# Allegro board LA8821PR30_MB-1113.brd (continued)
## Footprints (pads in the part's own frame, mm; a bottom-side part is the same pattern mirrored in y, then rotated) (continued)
BELLW_80019-1021_52P
  round 1.6 hole 1.6 unplated: (-25.55,-1.8) (1.95,-1.8)
  oval 0.61x2.007 smd: 1(0,0) 3(-0.8,0) 5(-1.6,0) 7(-2.4,0) 9(-3.2,0) 11(-4,0) 13(-4.8,0) 15(-5.6,0) 17(-9.6,0) 19(-10.4,0) 21(-11.2,0) 23(-12,0) 25(-12.8,0) 27(-13.6,0) 29(-14.4,0) 31(-15.2,0) 33(-16,0) 35(-16.8,0) 37(-17.6,0) 39(-18.4,0) 41(-19.2,0) 43(-20,0) 45(-20.8,0) 47(-21.6,0) 49(-22.4,0) 51(-23.2,0)
  oval 0.61x1.524 hole 0.457x0.914: 2(-0.4,-2.4) 4(-1.2,-2.4) 6(-2,-2.4) 8(-2.8,-2.4) 10(-3.6,-2.4) 12(-4.4,-2.4) 14(-5.2,-2.4) 16(-6,-2.4) 18(-10,-2.4) 20(-10.8,-2.4) 22(-11.6,-2.4) 24(-12.4,-2.4) 26(-13.2,-2.4) 28(-14,-2.4) 30(-14.8,-2.4) 32(-15.6,-2.4) 34(-16.4,-2.4) 36(-17.2,-2.4) 38(-18,-2.4) 40(-18.8,-2.4) 42(-19.6,-2.4) 44(-20.4,-2.4) 46(-21.2,-2.4) 48(-22,-2.4) 50(-22.8,-2.4) 52(-23.6,-2.4)
  oval 1.549x2.769 hole 0.787x2.007: 53(5.075,-8.4) 54(-28.675,-8.4)
BSS138-G_SOT23-3
  oval 1.016x1.524 smd: 1(0,0) 2(0.965,2.083) 3(-0.965,2.083)
BSS138_NL_SOT23-3
  oval 1.016x1.524 smd: 1(0,0) 2(0.965,2.083) 3(-0.965,2.083)
BZT52-B5V6S_SOD323-2
  rect 0.559x0.813 smd: 1(0,0) 2(2.305,0)
C_0402NEW
  rect 0.508x0.559 smd: 1(0,0) 2(0.914,0)
C_0603NEW
  rect 0.635x0.889 smd: 1(0,0) 2(1.397,0)
C_0805NEW
  rect 0.813x1.397 smd: 1(0,0) 2(1.702,0)
C_B
  rect 1.549x2.464 smd: 1(0,0) 2(3.378,0)
C_B2
  rect 1.346x2.692 smd: 1(0,0) 2(-2.75,0)
C_D2
  rect 2.388x2.794 smd: 1(0,0) 2(6.4,0)
C_D2E
  rect 2.388x2.896 smd: 1(0,0) 2(6.1,0)
D_EC31QS04
  rect 2.235x2.032 smd: 1(1.9,0) 2(-1.9,0)
D_RCLAMP0524PPTCT
  oval 0.203x0.686 smd: 1(0,0) 2(0.5,0) 4(1.5,0) 5(2,0) 6(2,0.875) 7(1.5,0.875) 9(0.5,0.875) 10(0,0.875)
  oval 0.406x1.549 smd: 3(1,0.437)
DE303DLHCTR_LGA14_3X5
  oval 0.61x1.092 smd: 1(0,0) 2(0.8,0) 3(1.6,0) 4(2.4,0) 5(3.2,0) 6(4,0) 8(4,2.2) 9(3.2,2.2) 10(2.4,2.2) 11(1.6,2.2) 12(0.8,2.2) 13(0,2.2)
  oval 1.092x0.61 smd: 7(4.1,1.1) 14(-0.1,1.1)
DMN66D0LDW-7_SOT363-6
  oval 0.432x0.61 smd: 1(0,0) 2(0.65,0) 3(1.3,0) 4(1.3,1.9) 5(0.65,1.9) 6(0,1.9)
E-T_1001-F36E-03R_36P
  round 0.711 hole 0.711 unplated: (-1.25,-2.425) (9.75,-2.425)
  oval 0.381x1.143 smd: 1(0,0) 2(0,-4.85) 35(8.5,0) 36(8.5,-4.85)
  oval 0.254x1.143 smd: 3(0.5,0) 4(0.5,-4.85) 5(1,0) 6(1,-4.85) 7(1.5,0) 8(1.5,-4.85) 9(2,0) 10(2,-4.85) 11(2.5,0) 12(2.5,-4.85) 13(3,0) 14(3,-4.85) 15(3.5,0) 16(3.5,-4.85) 17(4,0) 18(4,-4.85) 19(4.5,0) 20(4.5,-4.85) 21(5,0) 22(5,-4.85) 23(5.5,0) 24(5.5,-4.85) 25(6,0) 26(6,-4.85) 27(6.5,0) 28(6.5,-4.85) 29(7,0) 30(7,-4.85) 31(7.5,0) 32(7.5,-4.85) 33(8,0) 34(8,-4.85)
  custom 0.4x0.4 smd: 37(10.7,-2.425) 38(-2.2,-2.425)
EMI-79X138
  rect 2.007x3.505 smd: 1(0,0)
F_1206L150PR
  rect 0.991x1.803 smd: 1(0,0) 2(2.8,0)
F_1812L075-24DR
  rect 1.778x3.15 smd: 1(0,0) 2(5.23,0)
FDMC7672S_MLP8-5
  oval 0.432x0.711 smd: 1(0,0) 2(0.65,0) 3(1.3,0) 4(1.95,0)
  custom 0.537x0.537 smd: 5(0.975,2.075)
FDMS6673BZ_POWER56-8-5
  oval 0.61x1.27 smd: 1(0,0) 2(1.27,0) 3(2.54,0) 4(3.81,0)
  custom 1.105x1.105 smd: 5(1.905,3.715)
FDV301N_NL_SOT23-3
  oval 1.016x1.524 smd: 1(0,0) 2(0.965,2.083) 3(-0.965,2.083)
FIDUCIAL_C40M80
  round 1.016 smd: 1(0,0)
FOX_GS73091-10272-7H_9P-T
  rect 0.66x5.004 smd: 1(0,0) 2(-1.5,0) 3(-3,0) 4(-4.5,0) 5(-6,0) 6(-7.5,0) 7(-9,0) 8(-10.5,0) 9(-12,0)
  rect 2.489x2.997 smd: 10(-14.5,4.45) 11(2.5,4.45)
G547I2P81U_MSOP8
  oval 0.381x1.549 smd: 1(0,0) 2(0.65,0) 3(1.3,0) 4(1.95,0) 5(1.95,4.37) 6(1.3,4.37) 7(0.65,4.37) 8(0,4.37)
GLZ5P1B_LL34-2
  oval 0.889x2.007 smd: 1(0,0) 2(3.1,0)
H_2P0N
  round 2.007 hole 2.007 unplated: (0,0)
H_2P0X2P5N
  oval 2.007x2.489 hole 2.007x2.489 unplated: (0,0)
H_2P3
  round 2.819 hole 2.311: 1(0,0)
H_3P2
  round 3.708 hole 3.2: 1(0,0)
H_4P0
  round 4.496 hole 3.988: 1(0,0)
H_4P5N
  round 4.496 hole 4.496 unplated: (0,0)
HRS_UPFL-R-SMT-1-10_3P
  rect 1.041x2.21 smd: 1(0,0) 3(2.95,0)
  rect 0.991x1.041 smd: 2(1.475,1.525)
INA199A2DCKR_SC70-6
  oval 0.406x0.889 smd: 1(0,0) 2(0.65,0) 3(1.3,0) 4(1.3,2.2) 5(0.65,2.2) 6(0,2.2)
IP4223CZ6_SO6
  oval 0.508x1.422 smd: 1(0,0) 2(0.95,0) 3(1.9,0) 4(1.9,2.35) 5(0.95,2.35) 6(0,2.35)
ISL9519HRTZ-T_TQFN28_4X4
  oval 0.203x1.092 smd: 1(0,0) 2(0.4,0) 3(0.8,0) 4(1.2,0) 5(1.6,0) 6(2,0) 7(2.4,0) 15(2.4,3.9) 16(2,3.9) 17(1.6,3.9) 18(1.2,3.9) 19(0.8,3.9) 20(0.4,3.9) 21(0,3.9)
  oval 1.092x0.203 smd: 8(3.15,0.75) 9(3.15,1.15) 10(3.15,1.55) 11(3.15,1.95) 12(3.15,2.35) 13(3.15,2.75) 14(3.15,3.15) 22(-0.75,3.15) 23(-0.75,2.75) 24(-0.75,2.35) 25(-0.75,1.95) 26(-0.75,1.55) 27(-0.75,1.15) 28(-0.75,0.75)
  rect 2.388x2.388 smd: 29(1.2,1.95)
ISL95835HRTZ-T_TQFN40_5X5
  oval 0.203x0.991 smd: 1(0,0) 2(0.4,0) 3(0.8,0) 4(1.2,0) 5(1.6,0) 6(2,0) 7(2.4,0) 8(2.8,0) 9(3.2,0) 10(3.6,0) 21(3.6,5.001) 22(3.2,5.001) 23(2.8,5.001) 24(2.4,5.001) 25(2,5.001) 26(1.6,5.001) 27(1.2,5.001) 28(0.8,5.001) 29(0.4,5.001) 30(0,5.001)
  oval 0.991x0.203 smd: 11(4.3,0.7) 12(4.3,1.1) 13(4.3,1.5) 14(4.3,1.9) 15(4.3,2.3) 16(4.3,2.7) 17(4.3,3.1) 18(4.3,3.5) 19(4.3,3.9) 20(4.3,4.3) 31(-0.7,4.3) 32(-0.7,3.9) 33(-0.7,3.5) 34(-0.7,3.1) 35(-0.7,2.7) 36(-0.7,2.3) 37(-0.7,1.9) 38(-0.7,1.5) 39(-0.7,1.1) 40(-0.7,0.7)
  rect 3.607x3.607 smd: 41(1.8,2.5)
IVY-BRIDGE_BGA_1023P
  round 0.381 smd: A4(1.154,-0.101) A5(1.804,-0.101) A57(27.577,-0.101) A58(28.228,-0.101) A59(28.878,-0.101) A61(29.528,-0.101) BC1(0.177,-20.581) BC61(29.528,-20.577) BD1(0.101,-21.227) BD3(0.751,-21.227) BD59(28.878,-21.227) BD61(29.528,-21.227) BE1(0.101,-21.878) BE3(0.751,-21.878) BE4(1.401,-21.878) BE58(28.228,-21.878) BE59(28.878,-21.878) BE61(29.528,-21.878) BG1(0.101,-22.528) BG3(0.751,-22.528) BG4(1.401,-22.528) BG5(2.051,-22.392) BG57(27.577,-22.528) BG58(28.228,-22.528) BG59(28.878,-22.528) BG61(29.528,-22.528) C3(0.504,-0.504) C4(1.194,-0.751) C58(28.228,-0.751) C59(28.878,-0.751) C61(29.528,-0.751) D1(0.101,-1.144) D3(0.751,-1.227) D59(28.878,-1.401) D61(29.528,-1.401) E1(0.101,-1.794) E61(29.528,-2.051)
  round 0.305 smd: A8(3.181,0) A9(4.045,0) A11(5.157,0) A13(6.021,0) A15(7.133,0) A17(7.997,0) A19(9.109,0) A21(9.973,0) A23(11.086,0) A25(12.041,0) A26(12.691,0) A28(13.341,0) A29(13.991,0) A31(14.642,0) A33(15.292,0) A34(15.942,0) A35(16.592,0) A37(17.243,0) A38(17.893,0) A39(18.543,0) A40(19.193,0) A42(19.854,0) A44(20.966,0) A45(21.83,0) A48(22.942,0) A49(23.806,0) A51(24.918,0) A53(25.782,0) A55(26.895,0) AA1(0,-9.748) AA3(0.729,-9.748) AA4(1.374,-9.85) AA6(2.246,-9.912) AA7(2.897,-9.912) AA8(3.547,-9.912) AA10(4.197,-9.912) AA11(4.847,-9.912) AA13(5.498,-9.912) AA14(6.148,-9.912) AA50(24.08,-9.812) AA51(24.73,-9.812) AA52(25.381,-9.812) AA53(26.031,-9.812) AA55(26.681,-9.812) AA56(27.331,-9.812) AB50(24.08,-10.462) AB51(24.73,-10.462) AB52(25.381,-10.462) AB53(26.031,-10.462) AB55(26.681,-10.462) AB56(27.331,-10.462) AB58(28.204,-10.137) AB59(28.9,-10.239) AB61(29.629,-10.066) AC1(0,-10.612) AC3(0.729,-10.612) AC4(1.374,-10.51) AC6(2.566,-10.902) AC8(3.217,-10.902) AC9(3.867,-10.902) AC10(4.517,-10.902) AC12(5.167,-10.902) AC61(29.629,-10.716) AD2(0.381,-11.168) AD4(1.425,-11.168) AD50(24.08,-11.248) AD51(24.73,-11.248) AD52(25.381,-11.248) AD53(26.031,-11.248) AD55(26.681,-11.248) AD56(27.331,-11.248) AD58(28.204,-11.013) AD59(28.9,-11.115) AD61(29.629,-11.367) AE6(2.241,-11.468) AE7(2.892,-11.468) AE8(3.542,-11.468) AE10(4.192,-11.468) AE11(4.842,-11.468) AF1(0,-11.724) AF3(0.729,-11.724) AF4(1.374,-11.826) AF50(24.08,-12.066) AF51(24.73,-12.066) AF52(25.381,-12.066) AF53(26.031,-12.066) AF55(26.681,-12.066) AF56(27.331,-12.066) AF58(28.204,-11.902) AF59(28.9,-12.004) AF61(29.629,-12.017) AG1(0,-12.588) AG3(0.729,-12.588) AG4(1.374,-12.486) AG6(2.272,-12.459) AG7(2.922,-12.459) AG8(3.572,-12.459) AG10(4.222,-12.459) AG11(4.873,-12.459) AG55(26.681,-12.717) AG56(27.331,-12.717) AG58(28.254,-12.664) AG59(28.9,-12.766) AG61(29.629,-12.766) AH2(0.381,-13.144) AH4(1.425,-13.144) AH58(28.204,-13.322) AH60(29.248,-13.322) AJ6(2.272,-13.449) AJ7(2.922,-13.449) AJ8(3.572,-13.449) AJ10(4.222,-13.449) AJ11(4.873,-13.449) AK1(0,-13.7) AK3(0.729,-13.7) AK4(1.374,-13.802) AK55(26.77,-13.707) AK56(27.42,-13.707) AK58(28.254,-13.98) AK59(28.9,-13.879) AK61(29.629,-13.879) AL1(0,-14.564) AL3(0.729,-14.564) AL4(1.374,-14.462) AL6(2.221,-14.44) AL7(2.871,-14.44) AL8(3.521,-14.44) AL10(4.172,-14.44) AL11(4.822,-14.44) AL13(5.472,-14.44) AL14(6.122,-14.44) AL15(6.773,-14.44) AL58(28.254,-14.641) AL59(28.9,-14.742) AL61(29.629,-14.742) AM2(0.381,-15.12) AM4(1.425,-15.12) AM13(5.472,-15.287) AM14(6.122,-15.287) AM15(6.773,-15.287) AM58(28.204,-15.298) AM60(29.248,-15.298) AN1(0,-15.676) AN3(0.729,-15.676) AN4(1.374,-15.778) AN54(26.3,-15.545) AN55(26.95,-15.545) AN57(27.601,-15.545) AN58(28.254,-15.956) AN59(28.9,-15.855) AN61(29.629,-15.855) AP6(2.302,-15.852) AP7(2.952,-15.852) AP8(3.603,-15.852) AP10(4.253,-15.852) AP11(4.903,-15.852) AP50(24.024,-16.11) AP51(24.675,-16.11) AP52(25.325,-16.11) AP53(25.975,-16.11) AP55(26.625,-16.11) AP56(27.276,-16.11) AR1(0,-16.54) AR3(0.729,-16.54) AR4(1.374,-16.438) AR6(2.292,-16.843) AR7(2.942,-16.843) AR8(3.593,-16.843) AR10(4.243,-16.843) AR11(4.893,-16.741) AR13(5.776,-16.696) AR14(6.342,-16.371) AR17(8.18,-16.447) AR19(9.17,-16.447) AR21(10.161,-16.43) AR22(10.726,-16.755) AR26(12.564,-16.498) AR28(13.554,-16.396) AR30(14.545,-16.704) AR32(15.111,-16.378) AR34(16.101,-16.427) AR36(17.092,-16.427) AR40(18.929,-16.371) AR41(19.495,-16.696) AR43(20.486,-16.62) AR45(21.476,-16.696) AR48(23.314,-16.696) AR58(28.254,-16.617) AR59(28.9,-16.718) AR61(29.629,-16.718) AT2(0.381,-17.096) AT4(1.425,-17.096) AT13(5.776,-17.346) AT14(6.342,-17.021) AT17(8.18,-17.097) AT19(9.17,-17.097) AT21(10.161,-17.08) AT22(10.726,-17.405) AT26(12.564,-17.148) AT28(13.554,-17.046) AT30(14.545,-17.354) AT32(15.111,-17.029) AT34(16.101,-17.077) AT36(17.092,-17.077) AT40(18.929,-17.021) AT41(19.495,-17.346) AT43(20.486,-17.27) AT45(21.476,-17.346) AT48(23.314,-17.346) AT49(23.879,-17.021) AT52(25.381,-17.101) AT54(26.031,-17.101) AT55(26.681,-17.101) AT56(27.331,-17.101) AT58(28.204,-17.275) AT60(29.248,-17.275) AU1(0,-17.652) AU3(0.729,-17.652) AU4(1.374,-17.754) AU6(2.241,-17.834) AU7(2.892,-17.834) AU11(4.633,-17.747) AU13(5.776,-17.996) AU14(6.342,-17.671) AU17(8.18,-17.747) AU19(9.17,-17.747) AU21(10.161,-17.73) AU22(10.726,-18.055) AU26(12.564,-17.798) AU28(13.554,-17.697) AU30(14.545,-18.004) AU32(15.111,-17.679) AU34(16.101,-17.727) AU36(17.092,-17.727) AU40(18.929,-17.671) AU49(23.879,-17.671) AU51(24.87,-17.747) AU58(28.254,-17.932) AU59(28.9,-17.831) AU61(29.629,-17.831) AV1(0,-18.516) AV3(0.729,-18.516) AV4(1.374,-18.414) AV9(3.617,-18.388) AV11(4.633,-18.398) AV14(6.342,-18.322) AV17(8.18,-18.398) AV19(9.17,-18.398) AV21(10.161,-18.38) AV22(10.726,-18.706) AV28(13.554,-18.347) AV30(14.545,-18.654) AV32(15.111,-18.329) AV34(16.101,-18.377) AV36(17.092,-18.377) AV40(18.929,-18.322) AV41(19.495,-17.996) AV43(20.486,-17.92) AV45(21.476,-17.996) AV48(23.314,-17.996) AV49(23.879,-18.322) AV51(24.87,-18.398) AV54(26.031,-18.091) AV55(26.681,-18.091) AV56(27.331,-18.091) AW7(2.627,-18.728) AW13(5.776,-18.647) AW26(12.564,-18.449) AW41(19.495,-18.647) AW43(20.486,-18.57) AW45(21.476,-18.647) AW48(23.314,-18.647) AW58(28.254,-18.593) AW59(28.9,-18.694) AW61(29.629,-18.694) AY2(0.381,-19.072) AY4(1.425,-19.072) AY9(3.617,-19.038) AY11(4.633,-19.048) AY13(5.776,-19.297) AY14(6.342,-18.972) AY17(8.18,-19.048) AY19(9.17,-19.048) AY21(10.161,-19.031) AY22(10.726,-19.356) AY26(12.564,-19.099) AY28(13.554,-18.997) AY30(14.545,-19.305) AY32(15.111,-18.979) AY34(16.101,-19.028) AY36(17.092,-19.028) AY40(18.929,-18.972) AY41(19.495,-19.297) AY43(20.486,-19.221) AY45(21.476,-19.297) AY48(23.314,-19.297) AY49(23.879,-18.972) AY51(24.87,-19.048) AY53(25.861,-19.048) AY55(26.851,-19.048) AY58(28.204,-19.251) AY60(29.248,-19.251) B6(2.625,-0.381) B10(4.601,-0.381) B14(6.577,-0.381) B18(8.553,-0.381) B22(10.529,-0.381) B43(20.41,-0.381) B46(22.386,-0.381) B50(24.362,-0.381) B54(26.338,-0.381) BA1(0,-19.629) BA3(0.729,-19.629) BA4(1.364,-19.883) BA7(2.627,-19.378) BA9(3.617,-19.688) BA11(4.633,-19.698) BA13(5.776,-19.947) BA14(6.342,-19.622) BA17(8.18,-19.698) BA19(9.17,-19.698) BA21(10.161,-19.681) BA22(10.726,-20.006) BA26(12.564,-19.749) BA28(13.554,-19.647) BA30(14.545,-19.955) BA32(15.111,-19.63) BA34(16.101,-19.678) BA36(17.092,-19.678) BA40(18.929,-19.622) BA41(19.495,-19.947) BA43(20.486,-19.871) BA45(21.476,-19.947) BA48(23.314,-19.947) BA49(23.879,-19.622) BA51(24.87,-19.698) BA53(25.861,-19.698) BA55(26.851,-19.698) BA58(28.254,-19.909) BA59(28.9,-19.807) BA61(29.629,-19.807) BB3(0.778,-20.314) BB7(2.627,-20.028) BB9(3.617,-20.338) BB11(4.633,-20.348) BB14(6.342,-20.272) BB17(8.18,-20.348) BB19(9.17,-20.348) BB21(10.161,-20.331) BB26(12.564,-20.399) BB28(13.554,-20.298) BB32(15.111,-20.28) BB34(16.101,-20.328) BB36(17.092,-20.328) BB40(18.929,-20.272) BB49(23.879,-20.272) BB51(24.87,-20.348) BB53(25.861,-20.348) BB55(26.851,-20.348) BC4(1.301,-20.881) BC5(1.962,-20.674) BC7(2.627,-20.679) BC13(5.776,-20.597) BC22(10.726,-20.656) BC30(14.545,-20.605) BC41(19.495,-20.597) BC43(20.486,-20.521) BC45(21.476,-20.597) BC48(23.314,-20.597) BC57(27.829,-20.873) BC59(28.845,-20.578) BD8(3.214,-21.203) BD9(3.872,-21.254) BD10(4.532,-21.254) BD12(5.19,-21.203) BD13(5.848,-21.254) BD14(6.508,-21.254) BD16(7.166,-21.203) BD17(7.824,-21.254) BD18(8.485,-21.254) BD19(9.142,-21.203) BD21(9.8,-21.254) BD22(10.461,-21.254) BD23(11.119,-21.203) BD25(11.776,-21.254) BD26(12.437,-21.254) BD27(13.095,-21.203) BD29(13.753,-21.254) BD30(14.413,-21.254) BD32(15.071,-21.203) BD33(15.729,-21.254) BD35(16.389,-21.254) BD36(17.047,-21.203) BD37(17.705,-21.254) BD39(18.365,-21.254) BD40(19.023,-21.203) BD42(19.681,-21.254) BD43(20.341,-21.254) BD44(20.999,-21.203) BD45(21.657,-21.254) BD46(22.317,-21.254) BD48(22.975,-21.203) BD49(23.633,-21.254) BD50(24.294,-21.254) BD52(24.951,-21.203) BD53(25.604,-21.203) BD54(26.255,-21.208) BD56(27.004,-21.138) BE5(2.048,-21.661) BE7(2.658,-21.899) BE9(3.77,-21.899) BE11(4.634,-21.899) BE13(5.746,-21.899) BE14(6.61,-21.899) BE17(7.723,-21.899) BE18(8.586,-21.899) BE21(9.699,-21.899) BE22(10.562,-21.899) BE24(11.675,-21.899) BE26(12.538,-21.899) BE28(13.651,-21.899) BE30(14.515,-21.899) BE33(15.627,-21.899) BE35(16.491,-21.899) BE37(17.603,-21.899) BE39(18.467,-21.899) BE41(19.579,-21.899) BE43(20.443,-21.899) BE45(21.555,-21.899) BE47(22.419,-21.899) BE49(23.532,-21.899) BE51(24.395,-21.899) BE53(25.458,-21.839) BE54(26.321,-21.855) BE57(27.474,-21.773) BF8(3.214,-22.247) BF12(5.19,-22.247) BF16(7.166,-22.247) BF19(9.142,-22.247) BF23(11.119,-22.247) BF27(13.095,-22.247) BF32(15.071,-22.247) BF36(17.047,-22.247) BF40(19.023,-22.247) BF44(20.999,-22.247) BF48(22.975,-22.247) BF52(24.951,-22.247) BF56(26.879,-22.19) BG7(2.658,-22.628) BG9(3.77,-22.628) BG11(4.634,-22.628) BG13(5.746,-22.628) BG14(6.61,-22.628) BG17(7.723,-22.628) BG18(8.586,-22.628) BG21(9.699,-22.628) BG22(10.562,-22.628) BG24(11.675,-22.628) BG26(12.538,-22.628) BG28(13.651,-22.628) BG30(14.515,-22.628) BG33(15.627,-22.628) BG35(16.491,-22.628) BG37(17.603,-22.628) BG39(18.467,-22.628) BG41(19.579,-22.628) BG43(20.443,-22.628) BG45(21.555,-22.628) BG47(22.419,-22.628) BG49(23.532,-22.628) BG51(24.395,-22.628) BG53(25.508,-22.628) BG54(26.371,-22.628) C5(2.056,-0.706) C8(3.181,-0.729) C9(4.045,-0.729) C11(5.157,-0.729) C13(6.021,-0.729) C15(7.133,-0.729) C17(7.997,-0.729) C19(9.109,-0.729) C21(9.973,-0.729) C23(11.086,-0.729) C26(12.302,-0.65) C27(13.143,-0.65) C29(14.017,-0.65) C32(14.89,-0.65) C34(15.731,-0.65) C35(16.605,-0.65) C37(17.479,-0.65) C39(18.319,-0.65) C40(19.193,-0.65) C42(19.854,-0.729) C44(20.966,-0.729) C45(21.83,-0.729) C48(22.942,-0.729) C49(23.806,-0.729) C51(24.918,-0.729) C53(25.782,-0.729) C55(26.895,-0.729) C57(27.678,-1.213) D4(1.51,-1.323) D6(2.625,-1.425) D8(3.283,-1.374) D9(3.943,-1.374) D10(4.601,-1.425) D12(5.259,-1.374) D13(5.919,-1.374) D14(6.577,-1.425) D16(7.235,-1.374) D17(7.895,-1.374) D18(8.553,-1.425) D19(9.211,-1.374) D21(9.871,-1.374) D22(10.529,-1.425) D23(11.187,-1.374) D24(11.726,-0.995) D26(12.302,-1.3) D27(13.092,-1.3) D29(13.966,-1.3) D32(14.84,-1.3) D34(15.68,-1.3) D35(16.554,-1.3) D37(17.428,-1.3) D39(18.269,-1.3) D40(19.117,-1.326) D42(19.747,-1.501) D43(20.41,-1.425) D44(21.068,-1.374) D45(21.728,-1.374) D46(22.386,-1.425) D48(23.044,-1.374) D49(23.704,-1.374) D50(24.362,-1.425) D52(25.02,-1.374) D53(25.68,-1.374) D54(26.338,-1.425) D58(28.236,-1.569) E3(0.702,-2.042) E5(1.611,-1.984) E14(6.112,-2.031) E21(9.981,-2.031) E25(11.771,-1.679) E26(12.716,-1.962) E28(13.504,-1.962) E29(14.322,-1.962) E32(14.972,-1.962) E34(15.759,-1.962) E35(16.409,-1.962) E37(17.227,-1.962) E38(18.015,-1.962) E40(18.833,-1.962) E55(26.824,-1.884) E59(28.878,-2.051) F6(2.574,-2.28) F8(3.565,-2.28) F10(4.555,-2.28) F13(5.546,-2.356) F14(6.112,-2.681) F15(7.022,-2.695) F17(7.949,-2.147) F19(8.94,-2.275) F21(9.981,-2.681) F22(10.636,-2.128) F25(11.644,-2.612) F26(12.716,-2.612) F28(13.504,-2.612) F29(14.322,-2.612) F32(14.972,-2.612) F34(15.759,-2.612) F35(16.409,-2.612) F37(17.227,-2.612) F38(18.015,-2.612) F40(18.833,-2.612) F42(19.808,-2.216) F43(20.458,-2.216) F45(21.449,-2.216) F48(23.286,-2.211) F49(23.852,-2.536) F51(24.843,-2.204) F53(25.833,-2.28) F55(26.824,-2.534) G1(0,-2.707) G3(0.729,-2.707) G4(1.374,-2.606) G6(2.574,-2.93) G8(3.565,-2.93) G10(4.555,-2.93) G13(5.546,-3.006) G17(7.949,-2.798) G19(8.94,-2.925) G22(10.636,-2.778) G42(19.808,-2.867) G43(20.458,-2.867) G45(21.449,-2.867) G48(23.286,-2.861) G51(24.843,-2.854) G53(25.833,-2.93) G55(26.824,-3.184) G58(28.055,-2.695) G59(28.8,-2.797) G61(29.629,-2.822) H2(0.381,-3.263) H4(1.425,-3.263) H6(2.574,-3.58) H8(3.565,-3.58) H10(4.555,-3.58) H13(5.546,-3.657) H14(6.112,-3.331) H17(7.949,-3.448) H19(8.94,-3.575) H21(9.981,-3.331) H22(10.636,-3.428) H25(11.644,-3.262) H26(12.716,-3.262) H28(13.504,-3.262) H29(14.322,-3.262) H32(14.972,-3.262) H34(15.759,-3.262) H35(16.409,-3.262) H37(17.227,-3.262) H38(18.015,-3.262) H40(18.833,-3.262) H43(20.458,-3.517) H45(21.449,-3.517) H48(23.286,-3.511) H49(23.852,-3.186) H51(24.843,-3.504) H53(25.833,-3.58) H58(28.004,-3.353) H60(29.128,-3.359) J1(0,-3.82) J3(0.729,-3.82) J4(1.374,-3.921) J14(6.112,-3.982) J21(9.981,-3.982) J25(11.644,-3.913) J26(12.716,-3.913) J28(13.504,-3.913) J29(14.322,-3.913) J32(14.972,-3.913) J34(15.759,-3.913) J35(16.409,-3.913) J37(17.227,-3.913) J38(18.015,-3.913) J40(18.833,-3.913) J42(19.808,-3.517) J49(23.852,-3.836) J55(26.824,-3.834) J58(28.114,-4.011) J59(28.761,-3.909) J61(29.629,-3.909) K1(0,-4.683) K3(0.729,-4.683) K4(1.374,-4.582) K6(2.297,-4.537) K7(2.947,-4.537) K8(3.598,-4.537) K10(4.248,-4.537) K11(4.898,-4.537) K13(5.546,-4.307) K15(6.895,-4.117) K17(7.949,-4.098) K19(8.94,-4.226) K22(10.636,-4.078) K42(19.808,-4.167) K43(20.458,-4.167) K45(21.449,-4.167) K48(23.286,-4.162) K49(23.852,-4.487) K51(24.843,-4.154) K53(25.833,-4.231) K58(28.254,-4.671) L51(24.843,-4.805) L53(25.833,-4.881) L55(26.737,-4.795) L56(27.387,-4.795) L59(28.9,-4.773) L61(29.629,-4.773) M2(0.381,-5.24) M4(1.425,-5.24) M6(2.246,-5.528) M7(2.897,-5.528) M8(3.547,-5.528) M10(4.197,-5.528) M11(4.847,-5.528) M58(28.204,-5.326) M60(29.248,-5.329) N1(0,-5.796) N3(0.729,-5.796) N4(1.374,-5.897) N50(24.08,-5.921) N51(24.73,-5.921) N52(25.381,-5.921) N53(26.031,-5.921) N55(26.681,-5.921) N56(27.331,-5.921) N58(27.983,-5.939) N59(28.712,-5.946) N61(29.629,-6.165) P1(0,-6.659) P3(0.729,-6.659) P4(1.374,-6.558) P6(2.302,-6.518) P7(2.952,-6.518) P9(3.603,-6.518) P10(4.253,-6.518) P11(4.903,-6.518) P50(24.08,-6.739) P51(24.73,-6.739) P52(25.381,-6.739) P53(26.031,-6.739) P55(26.681,-6.739) P56(27.331,-6.739) P58(28.204,-6.553) P59(28.9,-6.649) P61(29.629,-6.815) R2(0.381,-7.216) R4(1.425,-7.227) T1(0,-7.772) T3(0.729,-7.772) T4(1.372,-7.879) T50(24.08,-7.557) T51(24.73,-7.557) T52(25.381,-7.557) T53(26.031,-7.557) T55(26.681,-7.557) T56(27.331,-7.557) T58(28.204,-7.453) T59(28.9,-7.555) T61(29.629,-7.465) U6(2.257,-8.045) U7(2.907,-8.045) U8(3.557,-8.045) U10(4.207,-8.045) U11(4.857,-8.045) U13(5.508,-8.045) U14(6.158,-8.045) U15(6.808,-8.045) V4(1.374,-8.534) V50(24.08,-8.207) V51(24.73,-8.207) V52(25.381,-8.207) V53(26.031,-8.207) V55(26.681,-8.207) V56(27.331,-8.207) V58(28.204,-8.33) V59(28.9,-8.431) V61(29.629,-8.115) W1(0,-8.635) W3(0.729,-8.635) W6(2.246,-8.921) W7(2.897,-8.921) W8(3.547,-8.921) W10(4.197,-8.921) W11(4.847,-8.921) W13(5.498,-8.921) W14(6.148,-8.921) W15(6.798,-8.921) W50(24.08,-8.994) W51(24.73,-8.994) W52(25.381,-8.994) W53(26.031,-8.994) W55(26.681,-8.994) W56(27.331,-8.994) W61(29.629,-8.766) Y2(0.381,-9.192) Y4(1.425,-9.192) Y58(28.204,-9.231) Y59(28.9,-9.333) Y61(29.629,-9.416)
  round 0.356 smd: AA15(6.798,-9.912) AA46(22.262,-9.756) AB16(7.428,-10.201) AB17(8.114,-10.201) AB18(8.8,-10.201) AB20(9.485,-10.201) AB21(10.171,-10.201) AB47(22.739,-10.201) AB48(23.425,-10.201) AC13(5.818,-10.902) AC14(6.468,-10.902) AC46(22.262,-10.645) AD16(7.428,-11.09) AD17(8.114,-11.09) AD18(8.8,-11.09) AD20(9.485,-11.09) AD21(10.171,-11.09) AD47(22.739,-11.09) AD48(23.425,-11.09) AE13(5.492,-11.468) AE14(6.143,-11.468) AE15(6.793,-11.468) AE46(22.262,-11.534) AF16(7.428,-11.979) AF17(8.114,-11.979) AF18(8.8,-11.979) AF20(9.485,-11.979) AF21(10.171,-11.979) AF46(22.262,-12.423) AF47(22.739,-11.979) AF48(23.425,-11.979) AG13(5.523,-12.459) AG14(6.173,-12.459) AG15(6.823,-12.459) AG16(7.428,-12.868) AG17(8.114,-12.868) AG18(8.8,-12.868) AG20(9.485,-12.868) AG21(10.171,-12.868) AG47(22.739,-12.868) AG48(23.425,-12.868) AG50(24.08,-12.717) AG51(24.73,-12.717) AG52(25.381,-12.717) AG53(26.031,-12.717) AJ13(5.523,-13.449) AJ14(6.173,-13.449) AJ15(6.823,-13.373) AJ16(7.423,-13.655) AJ17(8.312,-13.655) AJ20(9.201,-13.655) AJ21(10.09,-13.655) AJ22(10.979,-13.655) AJ25(11.868,-13.655) AJ26(12.757,-13.655) AJ28(13.646,-13.655) AJ30(14.535,-13.655) AJ33(15.424,-13.655) AJ34(16.313,-13.655) AJ36(17.202,-13.655) AJ38(18.091,-13.655) AJ40(18.98,-13.655) AJ42(19.869,-13.655) AJ43(20.758,-13.655) AJ45(21.647,-13.655) AJ47(22.536,-13.655) AJ48(23.425,-13.655) AK50(24.169,-13.707) AK51(24.819,-13.707) AK52(25.47,-13.707) AK54(26.12,-13.707) AL16(7.423,-14.341) AL17(8.312,-14.341) AL20(9.201,-14.341) AL21(10.09,-14.341) AL22(10.979,-14.341) AL25(11.868,-14.341) AL26(12.757,-14.341) AL28(13.646,-14.341) AL30(14.535,-14.341) AL33(15.424,-14.341) AL34(16.313,-14.341) AL36(17.202,-14.341) AL38(18.091,-14.341) AL40(18.98,-14.341) AL42(19.869,-14.341) AL43(20.758,-14.341) AL45(21.647,-14.341) AL47(22.536,-14.341) AL48(23.425,-14.341) AM16(7.423,-15.027) AM17(8.312,-15.027) AM20(9.201,-15.027) AM21(10.09,-15.027) AM22(10.979,-15.027) AM25(11.868,-15.027) AM26(12.757,-15.027) AM28(13.646,-15.027) AM30(14.535,-15.027) AM33(15.424,-15.027) AM34(16.313,-15.027) AM36(17.202,-15.027) AM38(18.091,-15.027) AM40(18.98,-15.027) AM42(19.869,-15.027) AM43(20.758,-15.027) AM45(21.647,-15.027) AM47(22.536,-15.027) AM48(23.425,-15.027) AN16(7.423,-15.712) AN17(8.312,-15.712) AN20(9.201,-15.712) AN21(10.09,-15.712) AN22(10.979,-15.712) AN25(11.868,-15.712) AN26(12.757,-15.712) AN28(13.646,-15.712) AN30(14.535,-15.712) AN33(15.424,-15.712) AN34(16.313,-15.712) AN36(17.202,-15.712) AN38(18.091,-15.712) AN40(18.98,-15.712) AN42(19.869,-15.712) AN43(20.758,-15.712) AN45(21.647,-15.712) AN47(22.536,-15.712) AN48(23.425,-15.712) AN50(24.349,-15.545) AN52(25,-15.545) AN53(25.65,-15.545) K21(9.638,-4.545) K24(11.442,-4.548) K26(12.319,-4.563) K27(13.195,-4.563) K29(14.097,-4.563) K32(14.973,-4.563) K34(15.862,-4.563) K35(16.751,-4.537) K37(17.627,-4.537) K39(18.504,-4.537) L16(7.423,-5.044) L17(8.312,-5.044) L20(9.201,-5.044) L21(10.09,-5.044) L22(10.979,-5.044) L25(11.868,-5.044) L26(12.757,-5.044) L28(13.646,-5.044) L30(14.535,-5.044) L33(15.424,-5.044) L34(16.313,-5.044) L36(17.202,-5.044) L38(18.091,-5.044) L40(18.98,-5.044) L42(19.869,-5.044) L43(20.758,-5.044) L45(21.647,-5.044) L47(22.536,-5.044) L48(23.425,-5.044) M13(5.498,-5.528) M14(6.148,-5.528) M15(6.793,-5.311) N16(7.423,-5.73) N17(8.312,-5.73) N20(9.201,-5.73) N21(10.09,-5.73) N22(10.979,-5.73) N25(11.868,-5.73) N26(12.757,-5.73) N28(13.646,-5.73) N30(14.535,-5.73) N33(15.424,-5.73) N34(16.313,-5.73) N36(17.202,-5.73) N38(18.091,-5.73) N40(18.98,-5.73) N42(19.869,-5.73) N43(20.758,-5.73) N45(21.647,-5.73) N47(22.536,-5.73) N48(23.425,-5.73) P13(5.553,-6.518) P14(6.204,-6.518) P16(7.428,-6.645) P17(8.114,-6.645) P18(8.8,-6.645) P20(9.485,-6.645) P21(10.171,-6.645) P47(22.739,-6.645) P48(23.425,-6.645) R16(7.428,-7.534) R17(8.114,-7.534) R18(8.8,-7.534) R20(9.485,-7.534) R21(10.171,-7.534) R46(22.262,-7.089) T47(22.739,-7.534) T48(23.425,-7.534) U46(22.262,-7.978) V16(7.428,-8.423) V17(8.114,-8.423) V18(8.8,-8.423) V20(9.485,-8.423) V21(10.171,-8.423) V47(22.739,-8.423) V48(23.425,-8.423) W16(7.428,-9.312) W17(8.114,-9.312) W18(8.8,-9.312) W20(9.485,-9.312) W21(10.171,-9.312) W46(22.262,-8.867) Y47(22.739,-9.312) Y48(23.425,-9.312)
JUMP_43X39
  custom 0.191x0.191 smd: 1(0,0) 2(0.914,0)
JUMP_43X79
  custom 0.188x0.188 smd: 1(0,0) 2(1.1,0)
JUMP_43X118
  custom 0.187x0.187 smd: 1(0,0) 2(1.1,0)
KB9012BF-A3_LFBGA_128P
  round 0.229 smd: A1(0,0) A2(0.5,0) A3(1,0) A4(1.5,0) A5(2,0) A6(2.5,0) A7(3,0) A8(3.5,0) A9(4,0) A10(4.5,0) A11(5,0) A12(5.5,0) A13(6,0) B1(0,-0.5) B2(0.5,-0.5) B3(1,-0.5) B4(1.5,-0.5) B5(2,-0.5) B6(2.5,-0.5) B7(3,-0.5) B8(3.5,-0.5) B9(4,-0.5) B10(4.5,-0.5) B11(5,-0.5) B12(5.5,-0.5) B13(6,-0.5) C1(0,-1) C2(0.5,-1) C12(5.5,-1) C13(6,-1) D1(0,-1.5) D2(0.5,-1.5) D4(1.5,-1.5) D5(2,-1.5) D6(2.5,-1.5) D7(3,-1.5) D8(3.5,-1.5) D9(4,-1.5) D10(4.5,-1.5) D12(5.5,-1.5) D13(6,-1.5) E1(0,-2) E2(0.5,-2) E4(1.5,-2) E5(2,-2) E6(2.5,-2) E7(3,-2) E8(3.5,-2) E9(4,-2) E10(4.5,-2) E12(5.5,-2) E13(6,-2) F1(0,-2.5) F2(0.5,-2.5) F4(1.5,-2.5) F5(2,-2.5) F9(4,-2.5) F10(4.5,-2.5) F12(5.5,-2.5) F13(6,-2.5) G1(0,-3) G2(0.5,-3) G4(1.5,-3) G5(2,-3) G9(4,-3) G10(4.5,-3) G12(5.5,-3) G13(6,-3) H1(0,-3.5) H2(0.5,-3.5) H4(1.5,-3.5) H5(2,-3.5) H9(4,-3.5) H10(4.5,-3.5) H12(5.5,-3.5) H13(6,-3.5) J1(0,-4) J2(0.5,-4) J4(1.5,-4) J5(2,-4) J6(2.5,-4) J7(3,-4) J8(3.5,-4) J9(4,-4) J10(4.5,-4) J12(5.5,-4) J13(6,-4) K1(0,-4.5) K2(0.5,-4.5) K4(1.5,-4.5) K5(2,-4.5) K6(2.5,-4.5) K7(3,-4.5) K8(3.5,-4.5) K9(4,-4.5) K10(4.5,-4.5) K12(5.5,-4.5) K13(6,-4.5) L1(0,-5) L2(0.5,-5) L12(5.5,-5) L13(6,-5) M1(0,-5.5) M2(0.5,-5.5) M3(1,-5.5) M4(1.5,-5.5) M5(2,-5.5) M6(2.5,-5.5) M7(3,-5.5) M8(3.5,-5.5) M9(4,-5.5) M10(4.5,-5.5) M11(5,-5.5) M12(5.5,-5.5) M13(6,-5.5) N1(0,-6) N2(0.5,-6) N3(1,-6) N4(1.5,-6) N5(2,-6) N6(2.5,-6) N7(3,-6) N8(3.5,-6) N9(4,-6) N10(4.5,-6) N11(5,-6) N12(5.5,-6) N13(6,-6)
KC_FBMA-L11-160808-800LMT_2P
  rect 0.889x1.092 smd: 1(0,0) 2(1.5,0)
L_1812-1806
  oval 1.016x3.708 smd: 1(0,0) 2(4.013,0)
LED_27-11-T1D-CP1Q1RY-3C_2P
  rect 0.991x0.991 smd: 1(0,0) 2(1.9,0)
LXES4XBAA6-027_MSOP8
  oval 0.381x1.575 smd: 1(0,0) 2(0.65,0) 3(1.3,0) 4(1.95,0) 5(1.95,4.35) 6(1.3,4.35) 7(0.65,4.35) 8(0,4.35)
MT41K256M8DA-15E-M_FBGA_78P
  round 0.343 smd: A1(0,0) A2(0.8,0) A3(1.6,0) A7(4.8,0) A8(5.6,0) A9(6.4,0) B1(0,-0.8) B2(0.8,-0.8) B3(1.6,-0.8) B7(4.8,-0.8) B8(5.6,-0.8) B9(6.4,-0.8) C1(0,-1.6) C2(0.8,-1.6) C3(1.6,-1.6) C7(4.8,-1.6) C8(5.6,-1.6) C9(6.4,-1.6) D1(0,-2.4) D2(0.8,-2.4) D3(1.6,-2.4) D7(4.8,-2.4) D8(5.6,-2.4) D9(6.4,-2.4) E1(0,-3.2) E2(0.8,-3.2) E3(1.6,-3.2) E7(4.8,-3.2) E8(5.6,-3.2) E9(6.4,-3.2) F1(0,-4) F2(0.8,-4) F3(1.6,-4) F7(4.8,-4) F8(5.6,-4) F9(6.4,-4) G1(0,-4.8) G2(0.8,-4.8) G3(1.6,-4.8) G7(4.8,-4.8) G8(5.6,-4.8) G9(6.4,-4.8) H1(0,-5.6) H2(0.8,-5.6) H3(1.6,-5.6) H7(4.8,-5.6) H8(5.6,-5.6) H9(6.4,-5.6) J1(0,-6.4) J2(0.8,-6.4) J3(1.6,-6.4) J7(4.8,-6.4) J8(5.6,-6.4) J9(6.4,-6.4) K1(0,-7.2) K2(0.8,-7.2) K3(1.6,-7.2) K7(4.8,-7.2) K8(5.6,-7.2) K9(6.4,-7.2) L1(0,-8) L2(0.8,-8) L3(1.6,-8) L7(4.8,-8) L8(5.6,-8) L9(6.4,-8) M1(0,-8.8) M2(0.8,-8.8) M3(1.6,-8.8) M7(4.8,-8.8) M8(5.6,-8.8) M9(6.4,-8.8) N1(0,-9.6) N2(0.8,-9.6) N3(1.6,-9.6) N7(4.8,-9.6) N8(5.6,-9.6) N9(6.4,-9.6)
MURAT_BLM18AG601SN1D_L0603_2P
  rect 0.66x1.041 smd: 1(0,0) 2(1.2,0)
MURAT_BLM18BA220SN1D_2P
  oval 0.66x1.041 smd: 1(0,0) 2(1.2,0)
MURAT_BLM18BD102SN1D_L0603_2P
  rect 0.66x1.041 smd: 1(0,0) 2(1.2,0)
MURAT_DLW21SN670HQ2L_4P
  rect 0.889x0.406 smd: 1(0,0) 2(1.7,0) 3(1.7,0.8) 4(0,0.8)
MURAT_LQM21FN1R0N00D_2P
  rect 0.991x1.753 smd: 1(0,0) 2(1.5,0)
MURAT_LQM21FN100M80L_2P
  rect 0.991x1.753 smd: 1(0,0) 2(1.5,0)
PESD5V0U2BT_SOT23-3
  oval 1.016x1.524 smd: 1(0,0) 2(0.965,2.083) 3(-0.965,2.083)
R0402_0OHM-NEW
  rect 0.508x0.559 smd: 1(0,0) 2(0.914,0)
R0603_0OHM-NEW
  rect 0.635x0.889 smd: 1(0,0) 2(1.397,0)
R0805_0OHM-NEW
  rect 0.813x1.397 smd: 1(0,0) 2(1.702,0)
R_0402NEW
  rect 0.508x0.559 smd: 1(0,0) 2(0.914,0)
R_0603NEW
  rect 0.635x0.889 smd: 1(0,0) 2(1.397,0)
R_0805NEW
  rect 0.813x1.397 smd: 1(0,0) 2(1.702,0)
R_1206_4P-D
  custom 0.445x0.445 smd: 1(0,0) 4(5.004,0)
  custom 0.114x0.114 smd: 2(1.194,0) 3(3.81,0)
R_1206NEW
  rect 1.016x1.651 smd: 1(0,0) 2(2.667,0)
RB751S40T1_SOD523-2
  rect 0.406x0.406 smd: 1(0,0) 2(1.4,0)
RB751V-40_SOD323-2
  rect 0.787x0.889 smd: 1(0,0) 2(2.14,0)
RB751V-40GTE-17_SOD323-2
  rect 0.787x0.889 smd: 1(0,0) 2(2.1,0)
RHU002N06_SOT323-3
  oval 0.813x0.914 smd: 1(0,0) 2(0.65,1.6) 3(-0.65,1.6)
RT8207MZQW_WQFN20_3X3
  oval 0.203x0.991 smd: 1(0,0) 2(0.4,0) 3(0.8,0) 4(1.2,0) 5(1.6,0) 11(1.6,3.001) 12(1.2,3.001) 13(0.8,3.001) 14(0.4,3.001) 15(0,3.001)
  oval 0.991x0.203 smd: 6(2.3,0.7) 7(2.3,1.1) 8(2.3,1.5) 9(2.3,1.9) 10(2.3,2.3) 16(-0.7,2.3) 17(-0.7,1.9) 18(-0.7,1.5) 19(-0.7,1.1) 20(-0.7,0.7)
  rect 1.702x1.702 smd: 21(0.8,1.5)
RT8243BZQW_WQFN20_3X3
  oval 0.203x1.016 smd: 1(0,0) 2(0.4,0) 3(0.8,0) 4(1.2,0) 5(1.6,0) 11(1.6,2.975) 12(1.2,2.975) 13(0.8,2.975) 14(0.4,2.975) 15(0,2.975)
  oval 1.016x0.203 smd: 6(2.288,0.688) 7(2.288,1.088) 8(2.288,1.488) 9(2.288,1.888) 10(2.288,2.288) 16(-0.688,2.288) 17(-0.688,1.888) 18(-0.688,1.488) 19(-0.688,1.088) 20(-0.688,0.688)
  rect 1.702x1.702 smd: 21(0.8,1.488)
SDMK0340L-7-F_SOD323-2
  rect 1.346x0.66 smd: 1(0,0) 2(2.4,0)
SHORTPADS
  custom 0.19x0.19 smd: 1(-0.483,0) 2(0.483,0)
SI2301CDS-T1-GE3_SOT23-3
  oval 1.016x1.524 smd: 1(0,0) 2(0.965,2.083) 3(-0.965,2.083)
SI3457BDV-T1-E3_TSOP6
  oval 0.508x1.448 smd: 1(0,0) 2(1,0) 3(2,0) 4(2,2.425) 5(1,2.425) 6(0,2.425)
SIR472DP-T1-GE3_POWERPAK8-5
  oval 0.61x1.27 smd: 1(0,0) 2(1.27,0) 3(2.54,0) 4(3.81,0)
  custom 1.105x1.105 smd: 5(1.905,3.36)
SIR818DP-T1_POWERPAK-SO8-5
  oval 0.61x1.27 smd: 1(0,0) 2(1.27,0) 3(2.54,0) 4(3.81,0)
  custom 1.105x1.105 smd: 5(1.905,3.715)
SKY13351-378LF_QFN6_1X1
  oval 0.203x0.33 smd: 1(0,0) 3(0.7,0) 4(0.7,0.97) 5(0.35,0.97) 6(0,0.97)
  custom 0.195x0.195 smd: 2(0.35,0.485)
SLG55584AVTR_TDFN8_2X2
  oval 0.254x0.914 smd: 1(0,0) 2(0.5,0) 3(1,0) 4(1.5,0) 5(1.5,2.075) 6(1,2.075) 7(0.5,2.075) 8(0,2.075)
  rect 1.6x0.889 smd: 9(0.75,1.038)
SN74AHC1G08DCKR_SC70-5
  oval 0.381x1.295 smd: 1(0,0.15) 2(0.65,0.15) 3(1.3,0.15) 4(1.3,1.89) 5(0,1.89)
SN74CBT3257CPWR_TSSOP16
  oval 0.381x1.651 smd: 1(0,0) 2(0.65,0) 3(1.3,0) 4(1.95,0) 5(2.6,0) 6(3.25,0) 7(3.9,0) 8(4.55,0) 9(4.55,5.775) 10(3.9,5.775) 11(3.25,5.775) 12(2.6,5.775) 13(1.95,5.775) 14(1.3,5.775) 15(0.65,5.775) 16(0,5.775)
SN74LVC1G06DCKR_SC70-5
  oval 0.381x0.864 smd: 1(0,0) 2(0.65,0) 3(1.3,0) 4(1.3,1.74) 5(0,1.74)
SN74LVC1G07DCKR_SC70-5
  oval 0.381x0.864 smd: 1(0,0) 2(0.65,0) 3(1.3,0) 4(1.3,1.74) 5(0,1.74)
SSM3K7002FU_SC70-3
  oval 0.508x0.991 smd: 1(0,0) 2(0.65,1.9) 3(-0.65,1.9)
STM32F103RDY6TR_WLCSP_64P
  round 0.254 smd: A1(0,0) A2(0.5,0) A3(1,0) A4(1.5,0) A5(2,0) A6(2.5,0) A7(3,0) A8(3.5,0) B1(0,-0.5) B2(0.5,-0.5) B3(1,-0.5) B4(1.5,-0.5) B5(2,-0.5) B6(2.5,-0.5) B7(3,-0.5) B8(3.5,-0.5) C1(0,-1) C2(0.5,-1) C3(1,-1) C4(1.5,-1) C5(2,-1) C6(2.5,-1) C7(3,-1) C8(3.5,-1) D1(0,-1.5) D2(0.5,-1.5) D3(1,-1.5) D4(1.5,-1.5) D5(2,-1.5) D6(2.5,-1.5) D7(3,-1.5) D8(3.5,-1.5) E1(0,-2) E2(0.5,-2) E3(1,-2) E4(1.5,-2) E5(2,-2) E6(2.5,-2) E7(3,-2) E8(3.5,-2) F1(0,-2.5) F2(0.5,-2.5) F3(1,-2.5) F4(1.5,-2.5) F5(2,-2.5) F6(2.5,-2.5) F7(3,-2.5) F8(3.5,-2.5) G1(0,-3) G2(0.5,-3) G3(1,-3) G4(1.5,-3) G5(2,-3) G6(2.5,-3) G7(3,-3) G8(3.5,-3) H1(0,-3.5) H2(0.5,-3.5) H3(1,-3.5) H4(1.5,-3.5) H5(2,-3.5) H6(2.5,-3.5) H7(3,-3.5) H8(3.5,-3.5)
SW_EVQP3S01K_4P
  rect 1.651x1.041 smd: 1(0,0) 3(3.85,0)
  rect 1.651x1.041 hole 0.61: 2(-0.1,1.525) 4(3.95,1.525)
SW_SKQGABE010_4P
  rect 1.803x1.092 smd: 1(0,0) 2(6.2,0) 3(0,-3.7) 4(6.2,-3.7)
SW_WCM2012F2S_4P
  rect 0.889x0.406 smd: 1(0,0) 2(1.7,0) 3(1.7,-0.8) 4(0,-0.8)
SY8033BDBC_DFN10_3X3
  oval 0.305x0.559 smd: 1(0,0) 2(0.5,0) 3(1,0) 4(1.5,0) 5(2,0) 6(2,2.7) 7(1.5,2.7) 8(1,2.7) 9(0.5,2.7) 10(0,2.7)
  rect 2.591x1.753 smd: 11(1,1.35)
TAIWI_USB014-107CRL-TW_10P-T
  round 1.321 hole 0.914: 1(0,0) 2(-2.5,0) 3(-4.5,0) 4(-7,0) 6(-5.75,-1.5) 7(-3.5,-1.5) 8(-1.25,-1.5) 9(1,-1.5)
  round 1.168 hole 0.914: 5(-8,-1.5)
  round 1.016 hole 0.762: 10(-8.2,-2.77)
  oval 1.372x3.15 hole 0.61x2.388: 11(-9.9,-1.59) 12(2.9,-1.59)
  oval 1.372x2.667 hole 0.61x1.905: 13(-11.4,-10.35) 14(4.4,-10.35)
TAIYO_NRS4018T1R0NDGJ_2P
  rect 1.194x3.708 smd: 1(0,0) 2(2.8,0)
TOKO_FDSD0630-H-1R0M-P3_2P
  rect 2.159x3.505 smd: 1(0,0) 2(5.85,0)
TOKO_FDSD0630-H-2R2M-P3_2P
  rect 2.159x3.505 smd: 1(0,0) 2(5.85,0)
TOKO_FDSD0630-H-3R3M-P3_2P
  rect 2.159x3.505 smd: 1(0,0) 2(5.85,0)
TOKO_FDUE0640J-H_4P
  custom 0.686x0.686 smd: 1(0,0) 4(9.271,0)
  rect 2.362x0.508 smd: 2(1.448,0) 3(7.823,0)
TOKO_FDVE0630-H-R47M-P3_2P
  rect 2.007x3.505 smd: 1(0,0) 2(6,0)
TP0610K-T1-E3_SOT23-3
  oval 1.016x1.524 smd: 1(0,0) 2(0.965,2.083) 3(-0.965,2.083)
TPC12
  round 0.305 smd: 1(0,0)
TPS22966DPUR_SON14_2X3
  oval 0.203x0.762 smd: 1(0,0) 2(0.4,0) 3(0.8,0) 4(1.2,0) 5(1.6,0) 6(2,0) 7(2.4,0) 8(2.4,2.05) 9(2,2.05) 10(1.6,2.05) 11(1.2,2.05) 12(0.8,2.05) 13(0.4,2.05) 14(0,2.05)
  rect 2.489x0.889 smd: 15(1.2,1.025)
TPS51212DSCR_SON10_3X3
  oval 0.279x0.838 smd: 1(0,0) 2(0.5,0) 3(1,0) 4(1.5,0) 5(2,0) 6(2,2.95) 7(1.5,2.95) 8(1,2.95) 9(0.5,2.95) 10(0,2.95)
  custom 0.412x0.412 smd: 11(1,1.475)
TPS51461RGER_QFN24_4X4
  oval 0.254x1.041 smd: 1(0,0) 2(0.5,0) 3(1,0) 4(1.5,0) 5(2,0) 6(2.5,0) 13(2.5,3.95) 14(2,3.95) 15(1.5,3.95) 16(1,3.95) 17(0.5,3.95) 18(0,3.95)
  oval 1.041x0.254 smd: 7(3.225,0.725) 8(3.225,1.225) 9(3.225,1.725) 10(3.225,2.225) 11(3.225,2.725) 12(3.225,3.225) 19(-0.725,3.225) 20(-0.725,2.725) 21(-0.725,2.225) 22(-0.725,1.725) 23(-0.725,1.225) 24(-0.725,0.725)
  rect 2.54x2.54 smd: 25(1.25,1.975)
TX3GD20TR_LGA16_4X4
  oval 0.406x0.686 smd: 1(0,0) 2(0.65,0) 3(1.3,0) 4(1.95,0) 9(1.95,3.6) 10(1.3,3.6) 11(0.65,3.6) 12(0,3.6)
  oval 0.686x0.406 smd: 5(2.775,0.825) 6(2.775,1.475) 7(2.775,2.125) 8(2.775,2.775) 13(-0.825,2.775) 14(-0.825,2.125) 15(-0.825,1.475) 16(-0.825,0.825)
TYCO_2041084-6_6P
  oval 0.356x1.295 smd: 1(0,0) 2(-1,0) 3(-2,0) 4(-3,0) 5(-4,0) 6(-5,0)
  rect 2.489x1.905 smd: 7(-7.65,3.3) 8(2.65,3.3)
TYCO_2041119-1_52P
  round 1.6 hole 1.6 unplated: (-0.7,4.1)
  round 1.092 hole 1.092 unplated: (24.3,4.1)
  oval 0.61x2.007 smd: 1(0,0) 2(0.4,8.2) 3(0.8,0) 4(1.2,8.2) 5(1.6,0) 6(2,8.2) 7(2.4,0) 8(2.8,8.2) 9(3.2,0) 10(3.6,8.2) 11(4,0) 12(4.4,8.2) 13(4.8,0) 14(5.2,8.2) 15(5.6,0) 16(6,8.2) 17(9.6,0) 18(10,8.2) 19(10.4,0) 20(10.8,8.2) 21(11.2,0) 22(11.6,8.2) 23(12,0) 24(12.4,8.2) 25(12.8,0) 26(13.2,8.2) 27(13.6,0) 28(14,8.2) 29(14.4,0) 30(14.8,8.2) 31(15.2,0) 32(15.6,8.2) 33(16,0) 34(16.4,8.2) 35(16.8,0) 36(17.2,8.2) 37(17.6,0) 38(18,8.2) 39(18.4,0) 40(18.8,8.2) 41(19.2,0) 42(19.6,8.2) 43(20,0) 44(20.4,8.2) 45(20.8,0) 46(21.2,8.2) 47(21.6,0) 48(22,8.2) 49(22.4,0) 50(22.8,8.2) 51(23.2,0) 52(23.6,8.2)
  rect 2.311x3.2 smd: 53(-2.85,0.6) 54(26.45,0.6)
W25Q64CVSSIG_SO8
  oval 0.635x1.676 smd: 1(0,0) 2(1.27,0) 3(2.54,0) 4(3.81,0) 5(3.81,7.25) 6(2.54,7.25) 7(1.27,7.25) 8(0,7.25)
Y_CM31532768DZFT_2P
  rect 1.092x1.905 smd: 1(0,0) 2(2.5,0)
Y_X1H008000DI1H-W_4P
  rect 1.6x1.295 smd: 1(0,0) 2(3.6,0) 3(3.6,2.3) 4(0,2.3)
Y_X3G025000DI1H-H_4P
  rect 1.397x1.194 smd: 1(0,0) 2(2.2,0) 3(2.2,1.7) 4(0,1.7)

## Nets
1.5V_PG: PR45.1 PR518.2 PU401.4
1.5VSP_FB: PC407.2 PR408.2 PR409.1 PU401.6
1.5VSP_LX: PL401.1 PR406.1 PU401.2 PU401.3
1.5VSP_VIN: PC410.1 PJP401.1 PU401.8 PU401.9 PU401.10
1.8V_PG: PR44.1 PR517.2 PU400.4
1.8VSP_FB: PC401.2 PR401.2 PR404.1 PU400.6
1.8VSP_LX: PL400.1 PR400.1 PU400.2 PU400.3
1.8VSP_VIN: PC400.1 PJP400.1 PU400.8 PU400.9 PU400.10
1.35V_B+: PC300.1 PC302.1 PC303.1 PC304.1 PJP301.1 PQ1215.5 PR305.1
1.35V_FB: PC314.1 PR304.1 PR307.1 PU300.6
1.35V_TON: PR305.2 PU300.9
+0.675VS: CD129.1 CD132.1 CD133.1 CD135.1 CD136.1 CD139.1 CD140.1 CD142.1 PR120.2 R293.1 R1036.2 R1037.2 R1038.2 R1039.2 R1040.2 R1041.2 R1042.2 R1043.2 R1044.2 R1045.2 R1046.2 R1047.2 R1048.2 R1049.2 R1050.2 R1051.2 R1052.2 R1053.2 R1054.2 R1055.2 R1056.2 R1057.2 R1058.2 R1059.2 R1060.2 R1061.2 R1062.2 R1063.2 R1064.2 R1065.2 R1066.2 R1067.2 R1068.2 R1069.2 R1070.2 R1071.2 R1072.2 R1073.2 R1074.2 R1075.2 R1076.2 R1077.2 R1078.2 R1079.2 R1080.2 R1081.2 R1082.2 R1083.2 RC106.1 RD33.2 RD34.2
+0.675VSP: PC305.1 PC306.1 PR120.1 PU300.2 PU300.20
+1.5V_PWROK: PR521.1 R933.2
+1.05VM_VCCSUS: CH76.1 RH234.1 UH1.AR33 UH1.AU33
+1.5VS: JP1.2 PJP403.1 R296.1 RH211.2
+1.5VS_D: Q34.1 R296.2
+1.5VS_PWROK: PR518.1 R982.2
+1.05VS_SATA3: CH70.1 RH233.2 UH1.AA13 UH1.AF15 UH1.AG13 UH1.AG15
+1.05VS_VCC_SATA: CH75.1 RH41.2 RH292.2 UH1.AB15 UH1.AC13 UH1.AC15
+1.05VS_VCCA_A_DPL: CH86.1 CH87.1 LH7.2 UH1.BF40
+1.05VS_VCCA_B_DPL: CH88.1 CH89.1 LH8.2 UH1.BD40
+1.05VS_VCCAPLL_FDI: CH46.1 RH208.1 UH1.AP13 UH1.AP15
+1.05VS_VCCPQ: CC224.1 RH280.2 UCPU1.AM25 UCPU1.AN22
+1.5VS_WLAN: C707.1 C708.1 C709.1 C710.1 C711.1 JP1.1 JWLAN1.6 JWLAN1.28 JWLAN1.48
+1.8VS: PJP402.1 RC109.1 RH207.2
+1.8VS_PWROK: PR517.1 R934.2
+1.8VS_VCCPLL: CC172.1 CC174.1 CC175.1 CC176.1 RC109.2 UCPU1.BB3 UCPU1.BC1 UCPU1.BC4
+1.35V: CC181.1 CC182.1 CC183.1 CC184.1 CD1.1 CD2.1 CD3.1 CD4.1 CD5.1 CD6.1 CD7.1 CD8.1 CD29.1 CD30.1 CD33.1 CD34.1 CD37.1 CD38.1 CD41.1 CD42.1 CD57.1 CD58.1 CD59.1 CD60.1 CD61.1 CD62.1 CD63.1 CD64.1 CD85.1 CD86.1 CD87.1 CD88.1 CD89.1 CD90.1 CD91.1 CD92.1 CD125.1 CD126.1 PJP303.2 PR119.2 QC3.5 QC3.6 QC3.7 QC3.8 R289.1 RC75.1 RD17.1 RD18.1 RD21.1 RD22.1 UD1.A2 UD1.A9 UD1.B9 UD1.C1 UD1.D7 UD1.E2 UD1.E9 UD1.G2 UD1.G8 UD1.K1 UD1.K9 UD1.M1 UD1.M9 UD2.A2 UD2.A9 UD2.B9 UD2.C1 UD2.D7 UD2.E2 UD2.E9 UD2.G2 UD2.G8 UD2.K1 UD2.K9 UD2.M1 UD2.M9 UD3.A2 UD3.A9 UD3.B9 UD3.C1 UD3.D7 UD3.E2 UD3.E9 UD3.G2 UD3.G8 UD3.K1 UD3.K9 UD3.M1 UD3.M9 UD4.A2 UD4.A9 UD4.B9 UD4.C1 UD4.D7 UD4.E2 UD4.E9 UD4.G2 UD4.G8 UD4.K1 UD4.K9 UD4.M1 UD4.M9 UD5.A2 UD5.A9 UD5.B9 UD5.C1 UD5.D7 UD5.E2 UD5.E9 UD5.G2 UD5.G8 UD5.K1 UD5.K9 UD5.M1 UD5.M9 UD6.A2 UD6.A9 UD6.B9 UD6.C1 UD6.D7 UD6.E2 UD6.E9 UD6.G2 UD6.G8 UD6.K1 UD6.K9 UD6.M1 UD6.M9 UD7.A2 UD7.A9 UD7.B9 UD7.C1 UD7.D7 UD7.E2 UD7.E9 UD7.G2 UD7.G8 UD7.K1 UD7.K9 UD7.M1 UD7.M9 UD8.A2 UD8.A9 UD8.B9 UD8.C1 UD8.D7 UD8.E2 UD8.E9 UD8.G2 UD8.G8 UD8.K1 UD8.K9 UD8.M1 UD8.M9 UD9.A2 UD9.A9 UD9.B9 UD9.C1 UD9.D7 UD9.E2 UD9.E9 UD9.G2 UD9.G8 UD9.K1 UD9.K9 UD9.M1 UD9.M9 UD10.A2 UD10.A9 UD10.B9 UD10.C1 UD10.D7 UD10.E2 UD10.E9 UD10.G2 UD10.G8 UD10.K1 UD10.K9 UD10.M1 UD10.M9 UD11.A2 UD11.A9 UD11.B9 UD11.C1 UD11.D7 UD11.E2 UD11.E9 UD11.G2 UD11.G8 UD11.K1 UD11.K9 UD11.M1 UD11.M9 UD12.A2 UD12.A9 UD12.B9 UD12.C1 UD12.D7 UD12.E2 UD12.E9 UD12.G2 UD12.G8 UD12.K1 UD12.K9 UD12.M1 UD12.M9 UD13.A2 UD13.A9 UD13.B9 UD13.C1 UD13.D7 UD13.E2 UD13.E9 UD13.G2 UD13.G8 UD13.K1 UD13.K9 UD13.M1 UD13.M9 UD14.A2 UD14.A9 UD14.B9 UD14.C1 UD14.D7 UD14.E2 UD14.E9 UD14.G2 UD14.G8 UD14.K1 UD14.K9 UD14.M1 UD14.M9 UD15.A2 UD15.A9 UD15.B9 UD15.C1 UD15.D7 UD15.E2 UD15.E9 UD15.G2 UD15.G8 UD15.K1 UD15.K9 UD15.M1 UD15.M9 UD16.A2 UD16.A9 UD16.B9 UD16.C1 UD16.D7 UD16.E2 UD16.E9 UD16.G2 UD16.G8 UD16.K1 UD16.K9 UD16.M1 UD16.M9
+1.35V_CPU_VDDQ: CC138.1 CC160.1 CC161.1 CC162.1 CC163.1 CC164.1 CC165.1 CC166.1 CC181.2 CC182.2 CC183.2 CC184.2 CC218.1 CC223.1 CC231.1 CC232.1 CC233.1 CC234.1 CC235.1 CC236.1 CC237.1 CC238.1 CC239.1 CC240.1 CC241.1 CC242.1 QC3.1 QC3.2 QC3.3 R292.1 RC8.1 RC103.1 RC112.1 UCPU1.AJ28 UCPU1.AJ33 UCPU1.AJ36 UCPU1.AJ40 UCPU1.AL30 UCPU1.AL34 UCPU1.AL38 UCPU1.AL42 UCPU1.AM28 UCPU1.AM33 UCPU1.AM36 UCPU1.AM40 UCPU1.AN26 UCPU1.AN30 UCPU1.AN34 UCPU1.AN38 UCPU1.AR26 UCPU1.AR28 UCPU1.AR30 UCPU1.AR32 UCPU1.AR34 UCPU1.AR36 UCPU1.AR40 UCPU1.AV41 UCPU1.AW26 UCPU1.BA40 UCPU1.BB28 UCPU1.BG33
+1.35V_CPU_VDDQ_CHG: Q37.1 R292.2
+1.35V_D: Q35.6 R289.2
+1.35VS: PC308.1 PC312.1 PC314.2 PC981.1 PJP303.1 PL1210.1 PR304.2 PU300.5
+3V_D: Q5.1 R298.2
+3V_PCH: C352.1 CC65.1 CH6.1 CH52.1 CH53.1 CH59.1 CH63.1 DH2.2 Q41.1 R298.1 R517.2 R812.2 RC4.2 RH38.1 RH39.1 RH40.1 RH42.1 RH54.2 RH56.2 RH57.2 RH67.2 RH69.2 RH70.2 RH72.2 RH73.2 RH74.2 RH75.2 RH91.1 RH103.2 RH107.2 RH110.1 RH112.1 RH116.1 RH118.1 RH141.2 RH143.2 RH145.2 RH146.2 RH154.2 RH188.2 RH190.2 RH210.2 RH214.2 RH244.1 RH270.2 RH279.1 RH290.2 RH317.2 RH318.2 RH319.2 RH320.2 RH321.2 RH322.2 RH323.2 RH324.2 U48.8 UC1.5 UH1.AM27 UH1.N27 UH1.R27 UH1.R29 UH1.R33 UH1.R35 UH1.U27 UH1.U29 UH1.U33 UH1.U35
+3V_PCH_DSW: CH48.1 RH150.2 RH214.1 RH311.1 RH312.1 UH1.R12
+3V_VCCPSPI: CH47.1 RH210.1 UH1.Y19
+3VALW: C617.2 C1100.2 JIOL1.7 JLVDS2.17 PD9.3 PJP202.2 PJP204.2 PJP400.2 PJP401.2 PJP600.2 PR38.2 PR44.2 PR45.2 PR48.1 PR901.2 PR910.2 PR916.2 PR961.1 Q41.3 Q47.3 R216.1 R542.1 R543.1 R806.1 R887.1 R906.2 R907.2 R908.2 R909.2 R914.2 R915.2 R917.2 R918.2 R919.2 R920.2 R977.2 R1024.1 R1030.1 R1102.1 RC102.1 RH312.2 U654.6 U654.7 U655.1 U655.2 U655.6 U655.7
+3VALW_EC: C276.1 C277.1 C278.1 C279.1 C280.2 C281.2 L43.1 PR935.2 R216.2 R219.2 R221.2 R229.2 R230.2 R241.2 R603.1 R604.1 R811.2 R922.2 R930.1 R935.2 R952.2 R954.2 R981.2 R987.2 R990.2 R1021.2 U34.J4 U34.J7 U34.K7 U34.K12 U34.M12
+3VLP: DH4.3 PR43.2 PR512.2 PR515.2 R811.1 R921.2 R927.1 R936.2 R937.1 R938.2 R939.1 R940.1
+3VNS_PWR: C965.1 C966.1 C969.1 C970.1 C976.1 C977.1 C978.1 C979.1 JSATA1.22 QH8.1 R817.1 R854.2 R855.2 R1003.2 R1091.1 R1092.2 R1095.1 R1096.1 R1097.1 R1098.1 R1107.2 U636.A1 U636.A8 U636.F7 U636.G6 U636.G8 U636.H1 U637.1 U637.14 U638.15 U638.16
+3VS: C655.1 C719.1 C720.1 C721.1 C722.1 C1101.2 C1135.1 C1136.1 C1137.1 C1138.1 C1139.1 C1140.1 C1171.1 C1199.1 CC68.1 CD127.1 CD128.1 CH36.1 CH44.1 CH65.1 CH68.1 CH69.1 D90.5 DH3.2 FV1.1 JIOL1.6 JSATA1.2 JSATA1.24 JSATA1.39 JSATA1.41 JSATA1.52 JTP1.1 PR500.2 PR601.1 PR728.2 Q326.2 Q328.2 Q335.3 QH3.2 QH3.5 QH4.2 QH4.5 QH8.3 R218.1 R223.1 R224.1 R244.2 R247.2 R884.2 R975.2 R1033.2 R1084.1 R1086.1 R1094.2 R1103.2 RC42.2 RD42.1 RH29.1 RH32.1 RH35.1 RH37.1 RH95.2 RH98.2 RH99.2 RH100.2 RH174.2 RH180.2 RH181.2 RH193.2 RH196.2 RH197.2 RH230.1 RH248.1 RH257.2 RH258.2 RH262.2 RH263.2 RH271.2 RH274.1 RH276.1 RH281.1 RH282.1 RH294.2 RH298.2 RH301.2 RH302.2 RH303.2 RH304.2 RH307.2 RH308.2 RH325.1 RH326.1 RH327.1 RH328.1 RH329.1 RH330.1 RH331.1 RH332.1 RH333.1 RH334.1 RH335.1 RV1.2 RV2.2 U635.5 U652.5 U652.10 U652.19 U652.24 U652.28 U655.8 U655.9 UC2.5 UD17.7 UD17.8 UD18.7 UD18.8 UH1.AB19 UH1.AC19 UH1.AF6 UH1.BK28 UH1.R40 UH1.T39 UH1.U37 UH1.U51 UH5.5
+3VS_CAM: C1158.1 C1159.1 D50.5 JLVDS2.4 Q47.1
+3VS_TS: C1200.1 JLVDS1.17 Q335.1 R1084.2
+3VS_VCC_CLKF33: CH66.1 CH67.1 RH230.2 UH1.V37 UH1.V39
+3VS_WLAN: C712.1 C713.1 C714.1 C715.1 C716.1 C1168.1 JWLAN1.2 JWLAN1.24 JWLAN1.39 JWLAN1.41 JWLAN1.52 Q327.2 Q327.5 R942.1 R1018.2 R1019.2 R1020.1 U655.13 U655.14
+5V_CHGUSB: C265.1 C303.1 D74.8 JUSB1.1 U656.6 U656.7 U656.8
+5V_PCH: CH116.1 QH7.1 RH222.1 RH295.1
+5V_USB_P0: C1109.1 C1110.1 D82.8 JUSB2.1 U657.6 U657.7 U657.8
+5VALW: C961.2 C962.1 C963.1 C1098.2 C1161.1 C1167.1 C1172.1 C1173.1 JIOL1.5 LED1.2 LED2.2 LED3.2 LED4.2 LED5.2 PC307.2 PC506.1 PC601.2 PD901.3 PJP201.1 PJP203.1 PR303.1 PR603.2 PR904.2 PU300.12 PU500.7 PU600.18 QH7.3 R287.1 R295.1 R808.1 U654.1 U654.2 U654.4 U655.4 U656.2 U656.3 U657.2 U657.3 UI1.5
+5VS: C1099.2 C1102.2 C1146.2 C1153.1 C1162.1 C1198.1 CV13.1 F1.2 JFAN1.4 JIOL1.1 JIOL1.2 JIOL1.3 JIOL1.4 JLVDS2.9 JLVDS2.10 PR716.1 PR720.1 PR721.1 PR722.2 PR724.2 PR736.1 Q329.3 QH1.2 QV1.2 R886.2 R989.2 RH227.1 U654.13 U654.14 UV1.16
+5VS_KBL: C1059.1 F1.1 JBL1.4
+V1.05S_VCCP_PWRGOOD: PR500.1 PR604.2 PU500.1
+V1.05S_VCCPP_B+: PC500.1 PC501.1 PC502.1 PC503.1 PJP500.2 PQ1211.5
+V18R: C293.1 U34.L1
+VCC_CORE: CC219.1 CC220.1 PC858.1 PC859.1 PC860.1 PC861.1 PC862.1 PC890.1 PC891.1 PC892.1 PC893.1 PC894.1 PC913.1 PC914.1 PC915.1 PC916.1 PC980.1 PC984.1 PC986.1 PC993.1 PC1225.1 PC1226.1 PC1227.1 PC1228.1 PC1229.1 PC1230.1 PC1231.1 PC1232.1 PC1233.1 PC1234.1 PC1235.1 PC1236.1 PC1237.1 PC1238.1 PC1239.1 PC1240.1 PC1900.1 PC1901.1 PL704.1 RC97.1 UCPU1.A26 UCPU1.A29 UCPU1.A31 UCPU1.A34 UCPU1.A35 UCPU1.A38 UCPU1.A39 UCPU1.A42 UCPU1.C26 UCPU1.C27 UCPU1.C32 UCPU1.C34 UCPU1.C37 UCPU1.C39 UCPU1.C42 UCPU1.D27 UCPU1.D32 UCPU1.D34 UCPU1.D37 UCPU1.D39 UCPU1.D42 UCPU1.E26 UCPU1.E28 UCPU1.E32 UCPU1.E34 UCPU1.E37 UCPU1.E38 UCPU1.F25 UCPU1.F26 UCPU1.F28 UCPU1.F32 UCPU1.F34 UCPU1.F37 UCPU1.F38 UCPU1.F42 UCPU1.G42 UCPU1.H25 UCPU1.H26 UCPU1.H28 UCPU1.H29 UCPU1.H32 UCPU1.H34 UCPU1.H35 UCPU1.H37 UCPU1.H38 UCPU1.H40 UCPU1.J25 UCPU1.J26 UCPU1.J28 UCPU1.J29 UCPU1.J32 UCPU1.J34 UCPU1.J35 UCPU1.J37 UCPU1.J38 UCPU1.J40 UCPU1.J42 UCPU1.K26 UCPU1.K27 UCPU1.K29 UCPU1.K32 UCPU1.K34 UCPU1.K35 UCPU1.K37 UCPU1.K39 UCPU1.K42 UCPU1.L25 UCPU1.L28 UCPU1.L33 UCPU1.L36 UCPU1.L40 UCPU1.N26 UCPU1.N30 UCPU1.N34 UCPU1.N38
+VCC_GFXCORE_AXG: PC850.1 PC851.1 PC852.1 PC853.1 PC854.1 PC855.1 PC856.1 PC987.1 PC994.1 PC1256.1 PC1257.1 PC1258.1 PC1259.1 PC1260.1 PC1261.1 PC1285.1 PC1286.1 PC1287.1 PC1288.1 PC1289.1 PC1290.1 PC1291.1 PC1292.1 PC1293.1 PC1294.1 PC1295.1 PC1296.1 PC1903.1 PL701.1 RC135.1 UCPU1.AA46 UCPU1.AB47 UCPU1.AB50 UCPU1.AB51 UCPU1.AB52 UCPU1.AB53 UCPU1.AB55 UCPU1.AB56 UCPU1.AB58 UCPU1.AB59 UCPU1.AC61 UCPU1.AD47 UCPU1.AD48 UCPU1.AD50 UCPU1.AD51 UCPU1.AD52 UCPU1.AD53 UCPU1.AD55 UCPU1.AD56 UCPU1.AD58 UCPU1.AD59 UCPU1.AE46 UCPU1.N45 UCPU1.P47 UCPU1.P48 UCPU1.P50 UCPU1.P51 UCPU1.P52 UCPU1.P53 UCPU1.P55 UCPU1.P56 UCPU1.P61 UCPU1.T48 UCPU1.T58 UCPU1.T59 UCPU1.T61 UCPU1.U46 UCPU1.V47 UCPU1.V48 UCPU1.V50 UCPU1.V51 UCPU1.V52 UCPU1.V53 UCPU1.V55 UCPU1.V56 UCPU1.V58 UCPU1.V59 UCPU1.W50 UCPU1.W51 UCPU1.W52 UCPU1.W53 UCPU1.W55 UCPU1.W56 UCPU1.W61 UCPU1.Y48 UCPU1.Y61
+VCCA_DPLL_L: LH7.1 LH8.1 RH247.2
+VCCA_USBSUS: CH55.1 UH1.AU31
+VCCACLK: RH213.1 UH1.AC51
+VCCAFDI_VRM: RH211.1 UH1.AC39 UH1.AE19 UH1.AF17 UH1.AU19 UH1.AU21 UH1.AW18 UH1.AW21
+VCCAPLL_CPY: LH4.1 RH216.2
+VCCAPLL_CPY_PCH: CH49.1 LH4.2 UH1.AW31
+VCCAPLLEXP: CH35.1 LH3.2 UH1.AP19
+VCCAPLLEXP_R: LH3.1 RH201.1
+VCCDPLL_CPY: RH219.1 UH1.AP27
+VCCP: CC221.1 CC222.1 CH25.1 CH26.1 CH27.1 CH28.1 CH37.1 CH38.1 CH39.1 CH40.1 CH41.1 CH42.1 CH43.1 CH50.1 CH57.1 CH58.1 CH60.1 CH61.1 CH62.1 CH72.1 CH74.1 CH77.1 CH79.1 CH80.1 CH81.1 LH6.2 PC990.1 PC991.1 PC995.1 PC1262.1 PC1263.1 PC1264.1 PC1265.1 PC1266.1 PC1267.1 PC1268.1 PC1269.1 PC1270.1 PC1271.1 PC1272.1 PC1273.1 PC1297.1 PC1298.1 PC1299.1 PC1300.1 PC1301.1 PC1302.1 PC1303.1 PC1304.1 PC1305.1 PC1306.1 PC1307.1 PC1308.1 PC1309.1 PC1310.1 PC1311.1 PC1312.1 PC1313.1 PC1314.1 PC1315.1 PC1316.1 PC1317.1 PC1318.1 PC1319.1 PC1320.1 PC1321.1 PC1322.1 PC1323.1 PJP501.1 PJP502.1 PR717.1 PR719.1 PR725.1 R297.1 RC2.1 RC32.1 RC36.1 RC43.2 RC45.2 RC46.2 RC47.2 RC48.2 RC93.1 RC95.2 RC126.1 RC137.2 RH43.2 RH113.2 RH124.1 RH201.2 RH208.2 RH213.2 RH216.1 RH219.2 RH233.1 RH234.2 RH247.1 RH280.1 RH292.1 UCPU1.AA14 UCPU1.AA15 UCPU1.AB17 UCPU1.AB20 UCPU1.AC13 UCPU1.AD16 UCPU1.AD18 UCPU1.AD21 UCPU1.AE14 UCPU1.AE15 UCPU1.AF16 UCPU1.AF18 UCPU1.AF20 UCPU1.AF46 UCPU1.AG15 UCPU1.AG16 UCPU1.AG17 UCPU1.AG20 UCPU1.AG21 UCPU1.AG48 UCPU1.AG50 UCPU1.AG51 UCPU1.AJ14 UCPU1.AJ15 UCPU1.AJ17 UCPU1.AJ21 UCPU1.AJ25 UCPU1.AJ43 UCPU1.AJ47 UCPU1.AK50 UCPU1.AK51 UCPU1.AL14 UCPU1.AL15 UCPU1.AL16 UCPU1.AL20 UCPU1.AL22 UCPU1.AL26 UCPU1.AL45 UCPU1.AL48 UCPU1.AM16 UCPU1.AM17 UCPU1.AM21 UCPU1.AM43 UCPU1.AM47 UCPU1.AN20 UCPU1.AN42 UCPU1.AN45 UCPU1.AN48 UCPU1.W16 UCPU1.W17 UH1.AB21 UH1.AB23 UH1.AB27 UH1.AB29 UH1.AB31 UH1.AC21 UH1.AC23 UH1.AC27 UH1.AC29 UH1.AC31 UH1.AC35 UH1.AC37 UH1.AE21 UH1.AE23 UH1.AE27 UH1.AE29 UH1.AE31 UH1.AE37 UH1.AE39 UH1.AF21 UH1.AF23 UH1.AG21 UH1.AG23 UH1.AG25 UH1.AG27 UH1.AJ17 UH1.AJ21 UH1.AJ23 UH1.AJ25 UH1.AJ27 UH1.AJ29 UH1.AJ31 UH1.AK21 UH1.AK29 UH1.AK31 UH1.AK33 UH1.AM17 UH1.AM21 UH1.AM23 UH1.AM33 UH1.AM35 UH1.AP39 UH1.AR15 UH1.AR23 UH1.AR25 UH1.AR27 UH1.AR29 UH1.AT13 UH1.AU15 UH1.AU23 UH1.AU25 UH1.AU27 UH1.AU29 UH1.AU35 UH1.AW16 UH1.AW34 UH1.N18 UH1.R19 UH1.R23 UH1.R25 UH1.U19 UH1.U21 UH1.U23 UH1.U25 UH1.V19 UH1.V21 UH1.V23 UH1.V25 UH1.Y21 UH1.Y23 UH1.Y25 UH1.Y27 UH1.Y29 UH1.Y31
+VCCP_D: Q4.1 R297.2
+VCCRTCEXT: CH71.1 UH1.R15 UH1.U15
+VCCSA: CC167.1 CC168.1 CC169.1 CC170.1 CC171.1 CC225.1 CC226.1 CC227.1 CC228.1 CC229.1 CC230.1 PJP601.1 UCPU1.L17 UCPU1.L21 UCPU1.N16 UCPU1.N20 UCPU1.N22 UCPU1.P17 UCPU1.P20 UCPU1.R16 UCPU1.R18 UCPU1.R21 UCPU1.U15 UCPU1.V16 UCPU1.V17 UCPU1.V18 UCPU1.V21 UCPU1.W20
+VCCSA_BT: PR605.1 PU600.12
+VCCSA_BT_1: PC602.1 PR605.2
+VCCSA_EN: PR604.1 PU600.13
+VCCSA_PHASE: PC602.2 PC603.1 PL600.1 PU600.7 PU600.8 PU600.9 PU600.10 PU600.11
+VCCSA_PWR_SRC: PC612.2 PC613.1 PC614.2 PC615.2 PJP600.1 PU600.22 PU600.23 PU600.24
+VCCSATAPLL: CH73.1 LH6.1 UH1.AM2
+VCCSST: CH78.1 UH1.U17
+VCCSUS1: CH54.1 UH1.V13
+VCCSUSHDA: CH85.1 RH244.2 UH1.V31
